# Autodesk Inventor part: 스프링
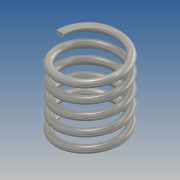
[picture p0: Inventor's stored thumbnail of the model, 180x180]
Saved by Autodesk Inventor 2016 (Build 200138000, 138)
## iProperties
Created: 2016-03
Part Number: 스프링
Material: 스테인레스 스틸
Document SubType Name: Modeling
Designer: Administrator
Density: 8 g/cm^3
Appearance: 반연마
Mass: 6.57144 g
Surface Area: 16.7195 cm^2
Volume: 0.821429 cm^3
Author: Administrator
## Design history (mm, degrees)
sketch "스케치1"
  geometry: L1 (0, 0)-(8.5, 0); L2 (8.5, 0)-(8.5, 20.5); L3 (8.5, 20.5)-(0, 20.5); L4 (0, 20.5)-(0, 0); C1 r 1 at (8.5, 0)
  constraints: 8 end point, 2 parallel, 1 centre point, 1 coincident, 1 horizontal, 1 perpendicular
  dimensions: "d0" = 20.5 distance of L1.end L2.end (derived); "d1" = 17 diameter of L2 L4; "d2" = 2 diameter of C1
feature "코일1" pitch "d3" = 10; turns "d5" = 5; dims "d4" = 20.5 (= d0), "d6" = 0, angle "d7" = 90 deg, angle "d8" = 90 deg, "d9" = 0, "d10" = 0
sketch "스케치2"
  geometry: L1 (4.1, 0)-(-21.424, 0); L2 (-21.424, 0)-(-21.424, -13.495); L3 (-21.424, -13.495)-(4.1, -13.495); L4 (4.1, -13.495)-(4.1, 0); 3 further points
  constraints: 8 end point, 2 parallel, 1 horizontal, 1 horizontal alignment, 1 perpendicular, 1 point on line
extrude "돌출1" cut sketch "스케치2" stored distance "d11" = 0; taper "d12" = 0 deg
sketch "스케치3"
  geometry: L1 (-2.819, 0)-(17.433, 0); L2 (17.433, 0)-(17.433, 5.421); L3 (17.433, 5.421)-(-2.819, 5.421); L4 (-2.819, 5.421)-(-2.819, 0); 3 further points
  constraints: 8 end point, 2 parallel, 1 horizontal, 1 horizontal alignment, 1 perpendicular, 1 point on line
extrude "돌출2" cut sketch "스케치3" stored distance "d13" = 0; taper "d14" = 0 deg
node "솔리드1"
